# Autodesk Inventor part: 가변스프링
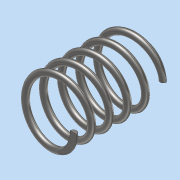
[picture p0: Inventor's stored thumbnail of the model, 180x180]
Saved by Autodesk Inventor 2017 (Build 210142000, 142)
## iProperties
Part Number: 가변스프링
Material: 스테인레스 스틸
Document SubType Name: Modeling
Designer: MRC
Density: 8 g/cm^3
Appearance: 반연마
Mass: 6.99701 g
Surface Area: 17.7559 cm^2
Volume: 0.874626 cm^3
Author: MRC
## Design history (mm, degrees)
sketch "스케치1"
  geometry: L1 (0, 0)-(9, 0); L2 (9, 0)-(9, 28.5); L3 (9, 28.5)-(0, 28.5); L4 (0, 28.5)-(0, 0); C1 r 1 at (9, 0)
  constraints: 8 end point, 2 parallel, 1 centre point, 1 coincident, 1 horizontal, 1 perpendicular
  dimensions: "d0" = 18 diameter of L2 L4; "d1" = 2 diameter of C1; "d2" = 28.5 distance of L3.end L1.start (derived)
feature "코일1" sketch "스케치1" pitch "d3" = 10; turns "d5" = 5; dims "d4" = 28.5 (= d2), "d6" = 0, angle "d7" = 90 deg, angle "d8" = 90 deg, "d9" = 0, "d10" = 0
sketch "스케치2"
  geometry: L1 (28.5, 19.913)-(0, 19.913); L2 (0, 19.913)-(0, -19.913); L3 (0, -19.913)-(28.5, -19.913); L4 (28.5, -19.913)-(28.5, 19.913); 2 further points
  constraints: 8 end point, 2 parallel, 1 coincident, 1 horizontal, 1 midpoint, 1 perpendicular
  dimensions: "d11" = 28.5 distance between parallel lines of L2 L4 (= d2); "d12" = 39.82623 distance of L3.end L1.start
extrude "돌출1" sketch "스케치2" stored distance "d13" = 67.75; taper "d14" = 0 deg
node "솔리드1"
